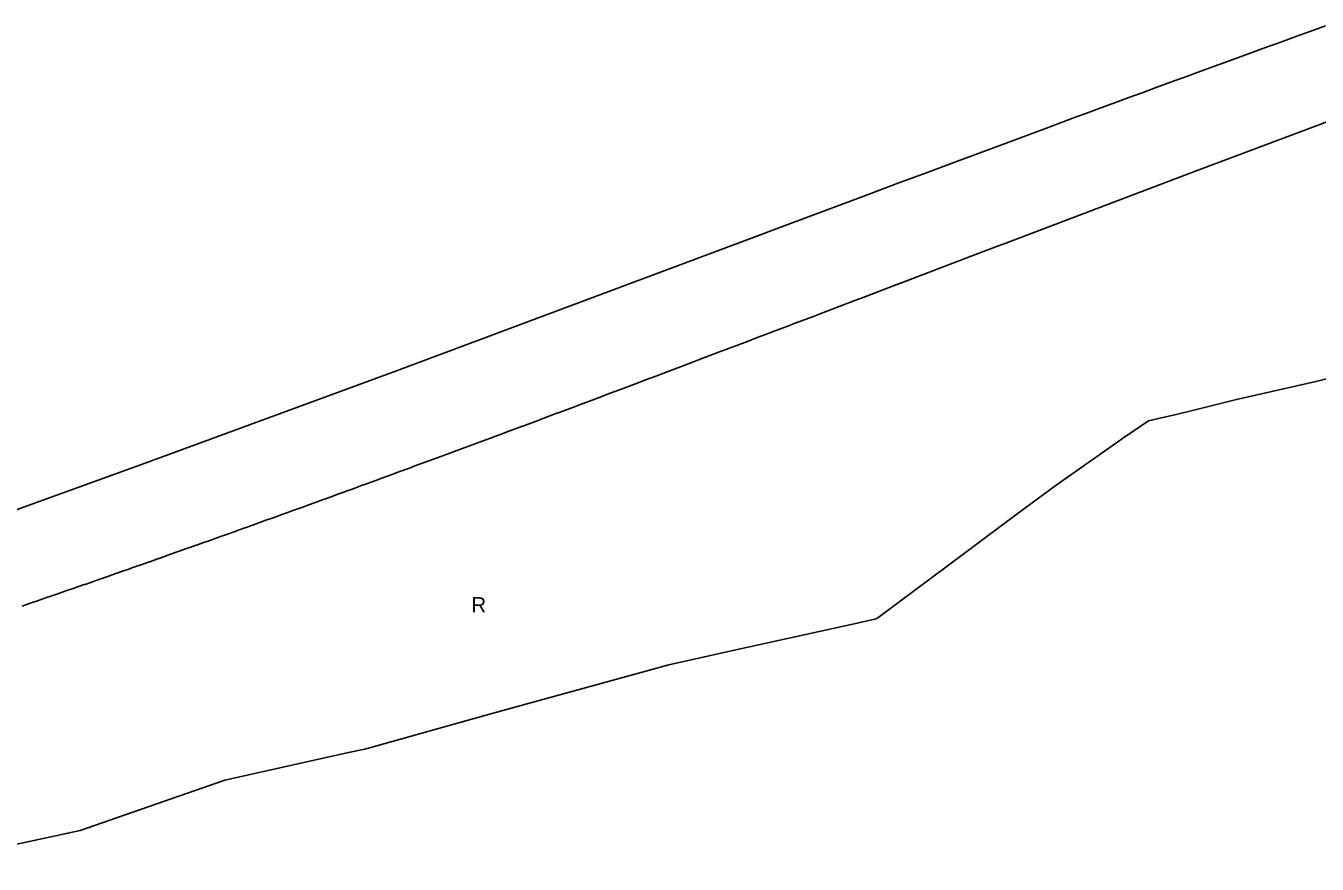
# Model space of a CAD drawing. Extents: x 7435758 to 7439981, y 5550649 to 5554049.
# Drawn here: x 7437107.4 to 7437552.2, y 5550718.5 to 5551007.2 of the extents above; entities that cross this region are included whole.
import ezdxf

# ---------------------------------------------------------------- set-up
doc = ezdxf.new("R2010")
doc.units = 0
doc.layers.add('linie_rozgraniczające', color=7, linetype='Continuous')
doc.layers.add('oznaczenia_przeznaczen', color=7, linetype='Continuous')

msp = doc.modelspace()

# ---------------------------------------------------------------- linework, layer by layer
at = {"layer": 'linie_rozgraniczające'}
for p, q in [((7437555.13, 5551007.18), (7437550.02, 5551005.34)), ((7437544.87, 5551003.47), (7437539.68, 5551001.59)), ((7437550.02, 5551005.34), (7437544.87, 5551003.47)), ((7437534.44, 5550999.69), (7437529.17, 5550997.77)), ((7437539.68, 5551001.59), (7437534.44, 5550999.69)), ((7437518.46, 5550993.87), (7437513.03, 5550991.88)), ((7437523.84, 5550995.83), (7437518.46, 5550993.87)), ((7437529.17, 5550997.77), (7437523.84, 5550995.83)), ((7437507.55, 5550989.88), (7437502.01, 5550987.85)), ((7437513.03, 5550991.88), (7437507.55, 5550989.88)), ((7437496.41, 5550985.79), (7437491.9, 5550984.13)), ((7437502.01, 5550987.85), (7437496.41, 5550985.79)), ((7437509.95, 5550957.05), (7437595.18, 5550988.94)), ((7437482.75, 5550980.77), (7437478.1, 5550979.05)), ((7437487.34, 5550982.46), (7437482.75, 5550980.77)), ((7437491.9, 5550984.13), (7437487.34, 5550982.46)), ((7437473.4, 5550977.32), (7437468.65, 5550975.57)), ((7437478.1, 5550979.05), (7437473.4, 5550977.32)), ((7437458.98, 5550971.99), (7437454.05, 5550970.16)), ((7437463.85, 5550973.79), (7437458.98, 5550971.99)), ((7437468.65, 5550975.57), (7437463.85, 5550973.79)), ((7437449.06, 5550968.31), (7437438.84, 5550964.52)), ((7437454.05, 5550970.16), (7437449.06, 5550968.31)), ((7437438.84, 5550964.52), (7437428.28, 5550960.59)), ((7437428.28, 5550960.59), (7437417.29, 5550956.51)), ((7437417.29, 5550956.51), (7437408.09, 5550953.08)), ((7437444.06, 5550932.04), (7437509.95, 5550957.05)), ((7437398.48, 5550949.49), (7437388.36, 5550945.71)), ((7437408.09, 5550953.08), (7437398.48, 5550949.49)), ((7437388.36, 5550945.71), (7437377.53, 5550941.67)), ((7437377.53, 5550941.67), (7437368.01, 5550938.1)), ((7437368.01, 5550938.1), (7437357.4, 5550934.13)), ((7437357.4, 5550934.13), (7437235.07, 5550888.44)), ((7437434.56, 5550928.42), (7437442.11, 5550931.3)), ((7437442.11, 5550931.3), (7437444.06, 5550932.04)), ((7437409.03, 5550918.7), (7437434.56, 5550928.42)), ((7437395.79, 5550913.66), (7437407.39, 5550918.07)), ((7437407.39, 5550918.07), (7437409.03, 5550918.7)), ((7437393.01, 5550912.6), (7437395.79, 5550913.66)), ((7437382.14, 5550908.46), (7437393.01, 5550912.6)), ((7437369.87, 5550903.8), (7437372.09, 5550904.65)), ((7437372.09, 5550904.65), (7437378.69, 5550907.15)), ((7437378.69, 5550907.15), (7437382.14, 5550908.46)), ((7437358.77, 5550899.59), (7437362.8, 5550901.12)), ((7437362.8, 5550901.12), (7437365.77, 5550902.24)), ((7437365.77, 5550902.24), (7437369.87, 5550903.8)), ((7437345.47, 5550894.55), (7437349.43, 5550896.05)), ((7437349.43, 5550896.05), (7437352.02, 5550897.03)), ((7437352.02, 5550897.03), (7437356, 5550898.54)), ((7437356, 5550898.54), (7437358.77, 5550899.59)), ((7437332.88, 5550889.79), (7437336.81, 5550891.27)), ((7437336.81, 5550891.27), (7437339.1, 5550892.14)), ((7437339.1, 5550892.14), (7437343.04, 5550893.63)), ((7437343.04, 5550893.63), (7437345.47, 5550894.55)), ((7437235.07, 5550888.44), (7437148.56, 5550856.57)), ((7437320.84, 5550885.24), (7437324.76, 5550886.72)), ((7437324.76, 5550886.72), (7437326.8, 5550887.49)), ((7437326.8, 5550887.49), (7437330.72, 5550888.97)), ((7437330.72, 5550888.97), (7437332.88, 5550889.79)), ((7437562.64, 5550887.41), (7437551.28, 5550884.61)), ((7437311.86, 5550881.86), (7437314.99, 5550883.04)), ((7437314.99, 5550883.04), (7437315, 5550883.05)), ((7437315, 5550883.05), (7437318.92, 5550884.52)), ((7437318.92, 5550884.52), (7437320.84, 5550885.24)), ((7437551.28, 5550884.61), (7437524.48, 5550878.48)), ((7437298.16, 5550876.72), (7437302.46, 5550878.33)), ((7437302.46, 5550878.33), (7437304.94, 5550879.27)), ((7437304.94, 5550879.27), (7437308.67, 5550880.66)), ((7437308.67, 5550880.66), (7437311.86, 5550881.86)), ((7437524.48, 5550878.48), (7437508.31, 5550874.47)), ((7437284.93, 5550871.77), (7437290.34, 5550873.79)), ((7437290.34, 5550873.79), (7437291.49, 5550874.22)), ((7437291.49, 5550874.22), (7437296.35, 5550876.04)), ((7437296.35, 5550876.04), (7437298.16, 5550876.72)), ((7437504.09, 5550873.5), (7437494.09, 5550871.19)), ((7437508.31, 5550874.47), (7437504.09, 5550873.5)), ((7437272.8, 5550867.25), (7437278.47, 5550869.36)), ((7437278.47, 5550869.36), (7437278.57, 5550869.4)), ((7437278.57, 5550869.4), (7437284.41, 5550871.58)), ((7437284.41, 5550871.58), (7437284.93, 5550871.77)), ((7437494.09, 5550871.19), (7437484.87, 5550864.89)), ((7437261.47, 5550863.04), (7437265.82, 5550864.65)), ((7437265.82, 5550864.65), (7437267.1, 5550865.13)), ((7437267.1, 5550865.13), (7437272.1, 5550866.99)), ((7437272.1, 5550866.99), (7437272.8, 5550867.25)), ((7437484.87, 5550864.89), (7437483.52, 5550863.97)), ((7437250.39, 5550858.94), (7437253.49, 5550860.08)), ((7437253.49, 5550860.08), (7437255.9, 5550860.97)), ((7437255.9, 5550860.97), (7437259.62, 5550862.35)), ((7437259.62, 5550862.35), (7437261.47, 5550863.04)), ((7437483.52, 5550863.97), (7437462.36, 5550849.06)), ((7437148.56, 5550856.57), (7437073.01, 5550829.36)), ((7437239.53, 5550854.94), (7437241.43, 5550855.64)), ((7437241.43, 5550855.64), (7437244.93, 5550856.92)), ((7437244.93, 5550856.92), (7437247.43, 5550857.84)), ((7437247.43, 5550857.84), (7437250.39, 5550858.94)), ((7437228.88, 5550851.02), (7437229.63, 5550851.3)), ((7437229.63, 5550851.3), (7437234.18, 5550852.97)), ((7437234.18, 5550852.97), (7437235.5, 5550853.46)), ((7437235.5, 5550853.46), (7437239.53, 5550854.94)), ((7437216.59, 5550846.54), (7437218.06, 5550847.07)), ((7437218.06, 5550847.07), (7437220.1, 5550847.81)), ((7437220.1, 5550847.81), (7437223.62, 5550849.1)), ((7437223.62, 5550849.1), (7437223.82, 5550849.18)), ((7437223.82, 5550849.18), (7437228.88, 5550851.02)), ((7437462.36, 5550849.06), (7437447, 5550837.74)), ((7437203.95, 5550841.94), (7437206.19, 5550842.75)), ((7437206.19, 5550842.75), (7437207.45, 5550843.21)), ((7437207.45, 5550843.21), (7437209.64, 5550844.01)), ((7437209.64, 5550844.01), (7437210.97, 5550844.49)), ((7437210.97, 5550844.49), (7437213.11, 5550845.27)), ((7437213.11, 5550845.27), (7437214.51, 5550845.78)), ((7437214.51, 5550845.78), (7437216.59, 5550846.54)), ((7437190.11, 5550836.94), (7437192.56, 5550837.83)), ((7437192.56, 5550837.83), (7437193.55, 5550838.18)), ((7437193.55, 5550838.18), (7437195.95, 5550839.05)), ((7437195.95, 5550839.05), (7437197, 5550839.43)), ((7437197, 5550839.43), (7437199.34, 5550840.27)), ((7437199.34, 5550840.27), (7437200.46, 5550840.68)), ((7437200.46, 5550840.68), (7437202.76, 5550841.51)), ((7437202.76, 5550841.51), (7437203.95, 5550841.94)), ((7437447, 5550837.74), (7437433.39, 5550827.59)), ((7437179.19, 5550833.02), (7437179.91, 5550833.28)), ((7437179.91, 5550833.28), (7437182.51, 5550834.21)), ((7437182.51, 5550834.21), (7437183.3, 5550834.49)), ((7437183.3, 5550834.49), (7437185.85, 5550835.41)), ((7437185.85, 5550835.41), (7437186.7, 5550835.72)), ((7437186.7, 5550835.72), (7437189.2, 5550836.61)), ((7437189.2, 5550836.61), (7437190.11, 5550836.94)), ((7437166.51, 5550828.5), (7437169.31, 5550829.49)), ((7437169.31, 5550829.49), (7437169.84, 5550829.68)), ((7437169.84, 5550829.68), (7437172.59, 5550830.66)), ((7437172.59, 5550830.66), (7437173.18, 5550830.88)), ((7437173.18, 5550830.88), (7437175.88, 5550831.84)), ((7437175.88, 5550831.84), (7437176.54, 5550832.07)), ((7437176.54, 5550832.07), (7437179.19, 5550833.02)), ((7437153.33, 5550823.83), (7437156.32, 5550824.88)), ((7437156.32, 5550824.88), (7437156.61, 5550824.99)), ((7437156.61, 5550824.99), (7437159.55, 5550826.03)), ((7437159.55, 5550826.03), (7437159.89, 5550826.15)), ((7437159.89, 5550826.15), (7437162.79, 5550827.18)), ((7437162.79, 5550827.18), (7437163.2, 5550827.32)), ((7437163.2, 5550827.32), (7437166.04, 5550828.33)), ((7437166.04, 5550828.33), (7437166.51, 5550828.5)), ((7437431.05, 5550825.84), (7437401.3, 5550803.68)), ((7437433.39, 5550827.59), (7437431.05, 5550825.84)), ((7437140.35, 5550819.27), (7437143.52, 5550820.38)), ((7437143.52, 5550820.38), (7437143.57, 5550820.4)), ((7437143.57, 5550820.4), (7437146.7, 5550821.49)), ((7437146.7, 5550821.49), (7437146.81, 5550821.53)), ((7437146.81, 5550821.53), (7437149.9, 5550822.62)), ((7437149.9, 5550822.62), (7437150.06, 5550822.68)), ((7437150.06, 5550822.68), (7437153.1, 5550823.75)), ((7437153.1, 5550823.75), (7437153.33, 5550823.83)), ((7437127.78, 5550814.88), (7437130.73, 5550815.9)), ((7437130.73, 5550815.9), (7437130.91, 5550815.97)), ((7437130.91, 5550815.97), (7437133.92, 5550817.02)), ((7437133.92, 5550817.02), (7437134.05, 5550817.06)), ((7437134.05, 5550817.06), (7437137.13, 5550818.14)), ((7437137.13, 5550818.14), (7437137.19, 5550818.16)), ((7437137.19, 5550818.16), (7437140.34, 5550819.26)), ((7437140.34, 5550819.26), (7437140.35, 5550819.27)), ((7437115.37, 5550810.58), (7437118.05, 5550811.51)), ((7437118.05, 5550811.51), (7437118.46, 5550811.65)), ((7437118.46, 5550811.65), (7437121.21, 5550812.6)), ((7437121.21, 5550812.6), (7437121.56, 5550812.72)), ((7437121.56, 5550812.72), (7437124.37, 5550813.7)), ((7437124.37, 5550813.7), (7437124.66, 5550813.8)), ((7437124.66, 5550813.8), (7437127.54, 5550814.8)), ((7437127.54, 5550814.8), (7437127.78, 5550814.88)), ((7437106.15, 5550807.42), (7437108.65, 5550808.27)), ((7437108.65, 5550808.27), (7437109.21, 5550808.47)), ((7437109.21, 5550808.47), (7437111.78, 5550809.35)), ((7437111.78, 5550809.35), (7437112.29, 5550809.52)), ((7437112.29, 5550809.52), (7437114.91, 5550810.43)), ((7437114.91, 5550810.43), (7437115.37, 5550810.58)), ((7437400.33, 5550803), (7437390.61, 5550800.84)), ((7437401.3, 5550803.68), (7437400.33, 5550803)), ((7437390.61, 5550800.84), (7437350.91, 5550792.05)), ((7437350.91, 5550792.05), (7437328.86, 5550787.12)), ((7437328.86, 5550787.12), (7437268.42, 5550770.5)), ((7437268.42, 5550770.5), (7437224.12, 5550758.17)), ((7437224.12, 5550758.17), (7437218.57, 5550756.93)), ((7437218.57, 5550756.93), (7437175.95, 5550747.44)), ((7437175.95, 5550747.44), (7437126.08, 5550730.18)), ((7437126.08, 5550730.18), (7437072.37, 5550718.54))]:
    msp.add_line(p, q, dxfattribs=at)

# ---------------------------------------------------------------- texts
at = {"layer": 'oznaczenia_przeznaczen'}
msp.add_text('R', height=5.2, dxfattribs=at).set_placement((7437260.91, 5550805.27))

doc.saveas('drawing.dxf')
